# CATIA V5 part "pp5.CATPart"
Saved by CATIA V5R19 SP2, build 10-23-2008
Part number: pp5
Publications: "Line.1", "Line.2", "Line.3", "Plane.1", "Line.4", "Plane.2"
Bounding box of the stored display mesh (mm): x -10 to 0, y -110 to 100, z -50 to 0
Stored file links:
  C:\Users\Welcome\Documents\thinkm2\pp5.CATPart
  C:\Users\Welcome\Documents\thinkm2\Brasmeca.CATProduct
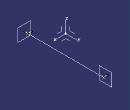
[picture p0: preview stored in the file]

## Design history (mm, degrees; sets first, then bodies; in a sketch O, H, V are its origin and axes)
AxisSystem1: origin (0, 0, 0), X (1, 0, 0), Y (0, 1, 0), Z (0, 0, 1)
Set1
  Point1: linked copy from another document
  Point2: linked copy from another document
Body1 (main body)
  Line1: type PtPt, FirstPoint Point1, SecondPoint Point2
  Line2: type PtDir, RefPoint Point1, Direction edge [XY plane of AxisSystem1 | ZX plane of AxisSystem1], Start 0, End -10
  Line3: type PtDir, RefPoint Point2, Direction edge [XY plane of AxisSystem1 | ZX plane of AxisSystem1], Start 0, End -10
  Plane1: type Normal, Curve Line3
  Line4: type PtDir, RefPoint Point1, Direction edge [YZ plane of AxisSystem1 | XY plane of AxisSystem1], Start 0, End -10
  Plane2: type Normal, Curve Line4, RefPoint vertex of Line4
